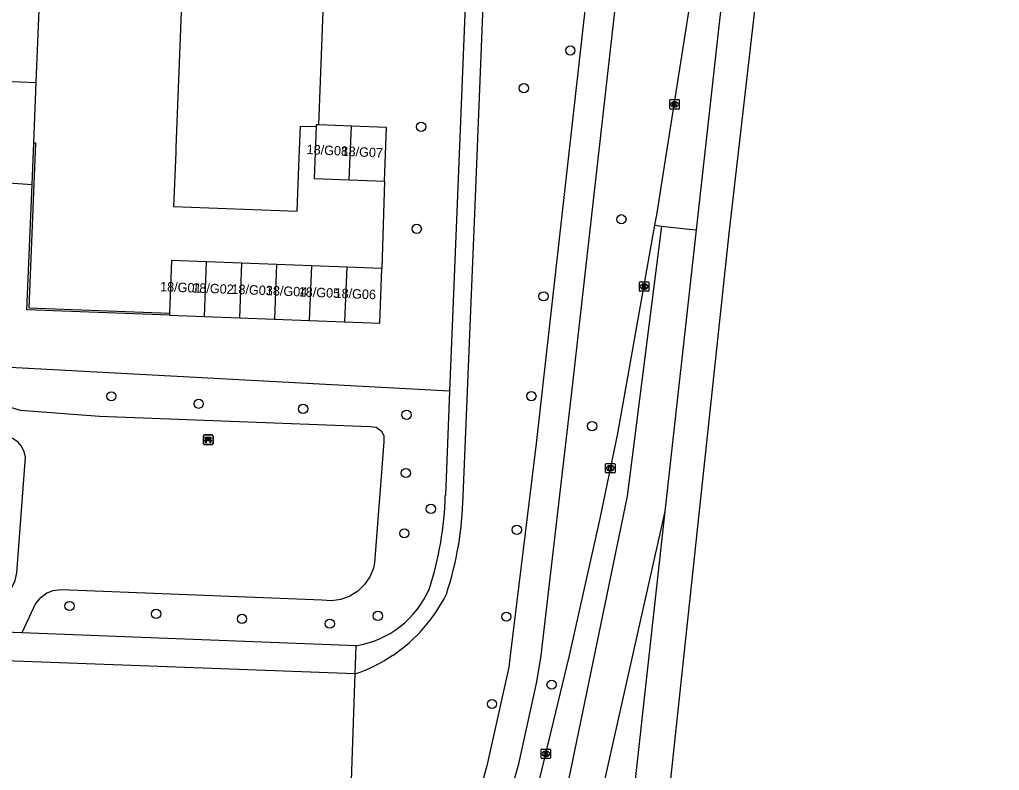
# Model space of a CAD drawing. Extents: x 161355 to 162026, y 386504 to 387459.
# Drawn here: x 161878.2 to 161982, y 386737.8 to 386817.3 of the extents above; entities that cross this region are included whole.
import ezdxf

# ---------------------------------------------------------------- set-up
doc = ezdxf.new("R2010")
doc.units = 0
for name, color, linetype in [('IMGEO_Bank', 7, 'Continuous'), ('IMGEO_Boom', 7, 'Continuous'), ('IMGEO_Fietspad_gesloten', 7, 'Continuous'), ('IMGEO_Groenvoorziening', 7, 'Continuous'), ('IMGEO_Kolk', 7, 'Continuous'), ('IMGEO_Loofbos', 7, 'Continuous'), ('IMGEO_Muur', 7, 'Continuous'), ('IMGEO_Pand', 7, 'Continuous'), ('IMGEO_Pand_nummerreeks', 7, 'Continuous'), ('IMGEO_Rijbaan_regionaal_gesloten', 7, 'Continuous'), ('IMGEO_Voetpad_halfverhard', 7, 'Continuous'), ('IMGEO_Voetpad_open', 7, 'Continuous')]:
    doc.layers.add(name, color=color, linetype=linetype)

msp = doc.modelspace()

# ---------------------------------------------------------------- linework, layer by layer
at = {"layer": 'IMGEO_Bank'}
for p, q in [((161897.72, 386772.41), (161897.72, 386773.25)), ((161897.72, 386773.25), (161897.72, 386772.41)), ((161897.79, 386773.34), (161898.63, 386773.34)), ((161898.63, 386773.34), (161897.79, 386773.34)), ((161898.03, 386772.84), (161898.03, 386772.95)), ((161898.07, 386772.95), (161898.07, 386772.84)), ((161898.36, 386772.95), (161898.08, 386772.95)), ((161898.08, 386772.84), (161898.36, 386772.84)), ((161898.36, 386772.84), (161898.36, 386772.95)), ((161898.41, 386772.95), (161898.41, 386772.84)), ((161898.72, 386773.26), (161898.72, 386772.42)), ((161898.72, 386772.42), (161898.72, 386773.26)), ((161898.64, 386772.34), (161897.8, 386772.34)), ((161897.8, 386772.34), (161898.64, 386772.34)), ((161898.41, 386772.73), (161898.02, 386772.73))]:
    msp.add_line(p, q, dxfattribs=at)
for points in [[(161897.96, 386772.73), (161897.82, 386772.73), (161897.93, 386772.84), (161898.02, 386772.84)], [(161898.02, 386772.95), (161897.93, 386772.95), (161897.93, 386773.12), (161898.5, 386773.12), (161898.5, 386772.95), (161898.41, 386772.95)], [(161898.41, 386772.84), (161898.5, 386772.84), (161898.61, 386772.73), (161898.47, 386772.73)], [(161898.01, 386772.73), (161898.01, 386772.52), (161897.97, 386772.52), (161897.97, 386772.73)], [(161898.46, 386772.73), (161898.46, 386772.52), (161898.42, 386772.52), (161898.42, 386772.73)]]:
    msp.add_lwpolyline(points, dxfattribs=at)
for centre, radius, start, end in [((161897.79, 386773.26), 0.0779, 92.4484, 184.2845), ((161897.79, 386773.26), 0.0779, 92.4484, 184.2845), ((161898.02, 386772.95), 0.00671, 2.8957, 87.1043), ((161898.02, 386772.84), 0.00671, 272.8957, 357.1043), ((161898.08, 386772.95), 0.00671, 92.8957, 177.1043), ((161898.08, 386772.84), 0.00671, 182.8957, 267.1043), ((161898.36, 386772.95), 0.00671, 2.8957, 87.1043), ((161898.36, 386772.84), 0.00671, 272.8957, 357.1043), ((161898.41, 386772.95), 0.00671, 92.8957, 177.1043), ((161898.41, 386772.84), 0.00671, 182.8957, 267.1043), ((161898.64, 386773.26), 0.0779, 2.4484, 94.2845), ((161898.64, 386773.26), 0.0779, 2.4484, 94.2845), ((161897.79, 386772.41), 0.0779, 182.4484, 274.2845), ((161897.79, 386772.41), 0.0779, 182.4484, 274.2845), ((161897.96, 386772.73), 0.00671, 2.8957, 87.1043), ((161898.02, 386772.73), 0.00671, 92.8957, 177.1043), ((161898.41, 386772.73), 0.00671, 2.8957, 87.1043), ((161898.47, 386772.73), 0.00671, 92.8957, 177.1043), ((161898.64, 386772.41), 0.0779, 272.4484, 4.2845), ((161898.64, 386772.41), 0.0779, 272.4484, 4.2845)]:
    msp.add_arc(centre, radius, start, end, dxfattribs=at)
at = {"layer": 'IMGEO_Boom'}
for centre in [(161936.55, 386814.07), (161931.63, 386810.08), (161920.76, 386805.99), (161941.96, 386796.19), (161920.29, 386795.18), (161933.72, 386788.03), (161887.95, 386777.44), (161897.2, 386776.65), (161932.43, 386777.45), (161908.26, 386776.11), (161919.21, 386775.48), (161938.86, 386774.28), (161919.14, 386769.31), (161921.79, 386765.51), (161930.89, 386763.3), (161918.98, 386762.92), (161883.53, 386755.23), (161892.7, 386754.39), (161901.79, 386753.86), (161916.18, 386754.18), (161929.78, 386754.1), (161911.08, 386753.35), (161934.57, 386746.89), (161928.26, 386744.85)]:
    msp.add_circle(centre, 0.489, dxfattribs=at)
at = {"layer": 'IMGEO_Fietspad_gesloten'}
for points in [[(161909.58, 386666.42), (161913.47, 386677.41), (161920.09, 386699.56), (161931.11, 386738.49), (161933.02, 386747.21), (161933.45, 386750), (161936.82, 386778.78), (161938.8, 386796.29), (161960.38, 386987.71), (161961.64, 387000), (161967.26, 387050.92)], [(161964.19, 387051.22), (161958.49, 387000), (161935.66, 386796.64), (161932.95, 386772.44), (161930.2, 386750), (161930.04, 386748.73), (161927.7, 386738.29), (161921.99, 386717.64), (161913.78, 386689.39)]]:
    msp.add_lwpolyline(points, dxfattribs=at)
at = {"layer": 'IMGEO_Groenvoorziening'}
for points in [[(161879.74, 386804.29), (161880, 386810.68)], [(161874.59, 386800.22), (161879.56, 386799.87)], [(161923.76, 386778), (161873.88, 386780.66)], [(161873.76, 386777.33), (161878.31, 386775.97), (161886.7, 386775.33), (161915.37, 386774.23), (161915.99, 386774.16), (161916.54, 386773.78), (161916.79, 386773.3), (161916.8, 386772.63), (161915.83, 386759.8), (161915.71, 386759.25), (161915.33, 386758.32), (161914.77, 386757.49), (161914.05, 386756.8), (161913.2, 386756.27), (161912.25, 386755.93), (161911.26, 386755.79), (161910.26, 386755.86), (161882.65, 386756.95), (161881.75, 386756.83), (161881.14, 386756.59), (161880.35, 386756), (161879.94, 386755.48), (161878.49, 386752.39)], [(161872.93, 386754.57), (161873.86, 386754.63), (161874.7, 386754.87), (161875.57, 386755.27), (161876.27, 386755.79), (161876.92, 386756.42), (161877.38, 386757.12), (161877.76, 386757.93), (161877.95, 386758.75), (161878.85, 386770.99), (161878.73, 386771.6), (161878.42, 386772.18), (161878.04, 386772.61), (161877.5, 386772.98), (161873.66, 386774.7)]]:
    msp.add_lwpolyline(points, dxfattribs=at)
at = {"layer": 'IMGEO_Kolk'}
for p, q in [((161947.09, 386807.94), (161947.09, 386808.79)), ((161947.17, 386808.86), (161948.02, 386808.86)), ((161947.58, 386808.64), (161947.6, 386808.64)), ((161947.6, 386808.08), (161947.58, 386808.08)), ((161948.09, 386808.79), (161948.09, 386807.94)), ((161948.02, 386807.86), (161947.17, 386807.86)), ((161943.87, 386788.63), (161943.87, 386789.49)), ((161943.94, 386789.56), (161944.79, 386789.56)), ((161944.87, 386789.49), (161944.87, 386788.63)), ((161944.79, 386788.56), (161943.94, 386788.56)), ((161944.35, 386789.34), (161944.38, 386789.34)), ((161944.38, 386788.78), (161944.35, 386788.78)), ((161940.29, 386769.39), (161940.29, 386770.24)), ((161940.36, 386770.32), (161941.21, 386770.32)), ((161940.78, 386770.1), (161940.8, 386770.1)), ((161941.29, 386770.24), (161941.29, 386769.39)), ((161941.21, 386769.32), (161940.36, 386769.32)), ((161940.8, 386769.54), (161940.77, 386769.54)), ((161933.45, 386739.15), (161933.45, 386740)), ((161933.52, 386740.07), (161934.38, 386740.07)), ((161933.94, 386739.85), (161933.96, 386739.85)), ((161934.45, 386740), (161934.45, 386739.15)), ((161934.38, 386739.07), (161933.52, 386739.07)), ((161933.96, 386739.29), (161933.93, 386739.29))]:
    msp.add_line(p, q, dxfattribs=at)
for points in [[(161947.09, 386807.94), (161947.09, 386808.79)], [(161947.17, 386808.86), (161948.02, 386808.86)], [(161947.41, 386808.56), (161947.54, 386808.56), (161947.54, 386808.41), (161947.66, 386808.56), (161947.83, 386808.56), (161947.68, 386808.41), (161947.84, 386808.16), (161947.68, 386808.16), (161947.6, 386808.33), (161947.54, 386808.26), (161947.54, 386808.16), (161947.41, 386808.16), (161947.41, 386808.56)], [(161948.09, 386808.79), (161948.09, 386807.94)], [(161948.02, 386807.86), (161947.17, 386807.86)], [(161943.87, 386788.63), (161943.87, 386789.49)], [(161943.94, 386789.56), (161944.79, 386789.56)], [(161944.87, 386789.49), (161944.87, 386788.63)], [(161944.79, 386788.56), (161943.94, 386788.56)], [(161944.19, 386789.26), (161944.31, 386789.26), (161944.31, 386789.11), (161944.44, 386789.26), (161944.6, 386789.26), (161944.46, 386789.11), (161944.61, 386788.86), (161944.46, 386788.86), (161944.37, 386789.02), (161944.31, 386788.96), (161944.31, 386788.86), (161944.19, 386788.86), (161944.19, 386789.26)], [(161940.29, 386769.39), (161940.29, 386770.24)], [(161940.36, 386770.32), (161941.21, 386770.32)], [(161940.61, 386770.02), (161940.73, 386770.02), (161940.73, 386769.87), (161940.86, 386770.02), (161941.03, 386770.02), (161940.88, 386769.87), (161941.03, 386769.62), (161940.88, 386769.62), (161940.8, 386769.78), (161940.73, 386769.71), (161940.73, 386769.62), (161940.61, 386769.62), (161940.61, 386770.02)], [(161941.29, 386770.24), (161941.29, 386769.39)], [(161941.21, 386769.32), (161940.36, 386769.32)], [(161933.45, 386739.15), (161933.45, 386740)], [(161933.52, 386740.07), (161934.38, 386740.07)], [(161933.77, 386739.77), (161933.89, 386739.77), (161933.89, 386739.62), (161934.02, 386739.77), (161934.19, 386739.77), (161934.04, 386739.62), (161934.19, 386739.37), (161934.04, 386739.37), (161933.96, 386739.54), (161933.89, 386739.47), (161933.89, 386739.37), (161933.77, 386739.37), (161933.77, 386739.77)], [(161934.45, 386740), (161934.45, 386739.15)], [(161934.38, 386739.07), (161933.52, 386739.07)]]:
    msp.add_lwpolyline(points, dxfattribs=at)
for centre, start, end in [((161947.17, 386808.79), 91.552, 178.448), ((161947.17, 386808.79), 91.552, 178.448), ((161948.02, 386808.79), 1.552, 88.448), ((161948.02, 386808.79), 1.552, 88.448), ((161947.17, 386807.94), 181.552, 268.448), ((161947.17, 386807.94), 181.552, 268.448), ((161948.02, 386807.94), 271.552, 358.448), ((161948.02, 386807.94), 271.552, 358.448), ((161943.94, 386789.48), 91.552, 178.448), ((161943.94, 386789.48), 91.552, 178.448), ((161944.79, 386789.48), 1.552, 88.448), ((161944.79, 386789.48), 1.552, 88.448), ((161943.94, 386788.64), 181.552, 268.448), ((161943.94, 386788.64), 181.552, 268.448), ((161944.79, 386788.64), 271.552, 358.448), ((161944.79, 386788.64), 271.552, 358.448), ((161940.36, 386770.24), 91.552, 178.448), ((161940.36, 386770.24), 91.552, 178.448), ((161941.21, 386770.24), 1.552, 88.448), ((161941.21, 386770.24), 1.552, 88.448), ((161940.36, 386769.39), 181.552, 268.448), ((161940.36, 386769.39), 181.552, 268.448), ((161941.21, 386769.39), 271.552, 358.448), ((161941.21, 386769.39), 271.552, 358.448), ((161933.53, 386740), 91.552, 178.448), ((161933.53, 386740), 91.552, 178.448), ((161934.37, 386740), 1.552, 88.448), ((161934.37, 386740), 1.552, 88.448), ((161933.53, 386739.15), 181.552, 268.448), ((161933.53, 386739.15), 181.552, 268.448), ((161934.37, 386739.15), 271.552, 358.448), ((161934.37, 386739.15), 271.552, 358.448)]:
    msp.add_arc(centre, 0.0765, start, end, dxfattribs=at)
for centre, major_axis, ratio, start_param, end_param in [((161947.58, 386808.36), (-0.387, 0.002), 0.722429, 4.712389, 7.853982), ((161947.6, 386808.36), (-0.39, 0.002), 0.717154, 1.570796, 4.712389), ((161944.35, 386789.06), (-0.387, 0.002), 0.722429, 4.712389, 7.853982), ((161944.38, 386789.06), (-0.39, 0.002), 0.717154, 1.570796, 4.712389), ((161940.77, 386769.82), (-0.387, 0.002), 0.722429, 4.712389, 7.853982), ((161940.8, 386769.82), (-0.39, 0.002), 0.717154, 1.570796, 4.712389), ((161933.94, 386739.57), (-0.387, 0.002), 0.722429, 4.712389, 7.853982), ((161933.96, 386739.57), (-0.39, 0.002), 0.717154, 1.570796, 4.712389)]:
    msp.add_ellipse(centre, major_axis=major_axis, ratio=ratio, start_param=start_param, end_param=end_param, dxfattribs=at)
at = {"layer": 'IMGEO_Loofbos'}
msp.add_lwpolyline([(161911.77, 386689.47), (161913.78, 386748.04)], dxfattribs=at)
at = {"layer": 'IMGEO_Muur'}
for points in [[(161879.74, 386804.29), (161879.94, 386804.28), (161879.22, 386786.8), (161894.11, 386786.23)], [(161879.56, 386799.87), (161879.74, 386804.29)], [(161894.1, 386786.03), (161879.01, 386786.61), (161879.56, 386799.87)], [(161916.86, 386800.24), (161916.59, 386790.98)]]:
    msp.add_lwpolyline(points, dxfattribs=at)
at = {"layer": 'IMGEO_Pand'}
for points in [[(161909.94, 386806.18), (161911.87, 386857.13), (161896.83, 386857.7), (161895.26, 386816.32), (161894.79, 386803.79), (161894.77, 386803.25), (161894.55, 386797.55), (161907.64, 386797.05), (161907.85, 386802.75), (161907.98, 386806.06), (161909.64, 386806)], [(161909.64, 386806), (161909.44, 386800.52), (161913.15, 386800.38)], [(161909.94, 386806.18), (161909.65, 386806.19), (161909.64, 386806)], [(161913.37, 386806.05), (161909.94, 386806.18)], [(161913.15, 386800.38), (161913.37, 386806.05)], [(161913.15, 386800.38), (161916.86, 386800.24), (161917.08, 386805.91), (161913.37, 386806.05)], [(161898.03, 386791.69), (161894.32, 386791.83), (161894.11, 386786.23)], [(161897.81, 386785.88), (161898.03, 386791.69)], [(161901.74, 386791.55), (161898.03, 386791.69)], [(161901.74, 386791.55), (161901.52, 386785.74)], [(161905.45, 386791.4), (161901.74, 386791.55)], [(161905.45, 386791.4), (161905.23, 386785.6)], [(161909.17, 386791.26), (161905.45, 386791.4)], [(161908.94, 386785.46), (161909.17, 386791.26)], [(161912.88, 386791.12), (161909.17, 386791.26)], [(161912.88, 386791.12), (161912.65, 386785.32)], [(161912.65, 386785.32), (161916.37, 386785.18), (161916.59, 386790.98), (161912.88, 386791.12)], [(161894.11, 386786.23), (161894.1, 386786.03)], [(161894.1, 386786.03), (161897.81, 386785.88)], [(161897.81, 386785.88), (161901.52, 386785.74)], [(161901.52, 386785.74), (161905.23, 386785.6)], [(161905.23, 386785.6), (161908.94, 386785.46)], [(161908.94, 386785.46), (161912.65, 386785.32)]]:
    msp.add_lwpolyline(points, dxfattribs=at)
at = {"layer": 'IMGEO_Rijbaan_regionaal_gesloten'}
for points in [[(161975.24, 387050.12), (161969.65, 387000), (161962.33, 386935.47), (161954.58, 386865.29), (161949.34, 386820), (161945.68, 386796.65), (161945.48, 386795.55)], [(161978.47, 387049.8), (161974.35, 387011.24), (161973.14, 387000.21), (161967.66, 386954.87), (161949.87, 386795.06)], [(161981.98, 387049.45), (161976.05, 386997.24), (161962.38, 386873.24), (161953.32, 386794.68), (161940.78, 386677.09), (161933.98, 386612.63), (161933.5, 386609.43), (161932.69, 386601.55), (161929.93, 386573.91), (161926.12, 386532.02)], [(161885.77, 386537.53), (161889.41, 386536.78), (161889.83, 386542.31), (161890.94, 386556.75), (161891.61, 386564.82), (161892.8, 386577.15), (161893.92, 386585.31), (161895.23, 386593.24), (161896.78, 386601.48), (161897.68, 386605.37), (161899.68, 386613.31), (161901.97, 386621.17), (161904.42, 386628.99), (161906.92, 386636.79), (161912.12, 386652.52), (161914.7, 386660.32), (161923.53, 386687.45), (161934.86, 386729.46), (161942.62, 386766.86), (161946.24, 386795.46)], [(161945.48, 386795.55), (161941.55, 386773.5), (161939.69, 386764.51), (161936.42, 386750), (161931.85, 386730.96), (161926.09, 386709.11), (161923.2, 386699.07), (161919.76, 386687.28), (161915.36, 386673.37), (161911.3, 386661.24), (161910.94, 386660.23)], [(161945.48, 386795.55), (161946.24, 386795.46)], [(161946.24, 386795.46), (161949.15, 386795.14), (161949.87, 386795.06)], [(161949.87, 386795.06), (161946.56, 386765.22)], [(161946.56, 386765.22), (161942.59, 386729.49), (161942.44, 386728.02), (161926.42, 386570.32), (161923.25, 386535.82), (161922.93, 386532.15)], [(161946.56, 386765.22), (161945.26, 386759.43), (161938.3, 386728.44)]]:
    msp.add_lwpolyline(points, dxfattribs=at)
at = {"layer": 'IMGEO_Voetpad_halfverhard'}
for points in [[(161925.21, 386766.87), (161926.46, 386797.66), (161928.84, 386856.82), (161934.63, 386878.76)], [(161927.42, 386868.61), (161924.56, 386797.86), (161923.76, 386778)], [(161923.76, 386778), (161923.32, 386766.94)]]:
    msp.add_lwpolyline(points, dxfattribs=at)
for centre, radius, start, end in [((161888.62, 386767.77), 34.7, 342.0341, 358.6274), ((161888.52, 386767.79), 36.7, 342.0593, 358.56), ((161912.28, 386761.08), 10.18, 278.9227, 336.8109), ((161908.37, 386763.99), 16.84, 303.8184, 333.5339), ((161908.41, 386763.84), 16.69, 288.7537, 303.9824)]:
    msp.add_arc(centre, radius, start, end, dxfattribs=at)
at = {"layer": 'IMGEO_Voetpad_open'}
for points in [[(161880, 386810.68), (161882.45, 386870.5)], [(161874.75, 386804.63), (161874.97, 386810.9), (161880, 386810.68)], [(161878.49, 386752.39), (161872.86, 386752.61)], [(161913.86, 386751.02), (161878.49, 386752.39)], [(161913.78, 386748.04), (161913.83, 386750), (161913.86, 386751.02)], [(161913.78, 386748.04), (161872.92, 386749.57)]]:
    msp.add_lwpolyline(points, dxfattribs=at)

# ---------------------------------------------------------------- texts
at = {"layer": 'IMGEO_Pand_nummerreeks'}
for s, rotation, p in [('18/G08', 357.2073, (161908.61, 386803.11)), ('18/G07', 357.2073, (161912.31, 386802.93)), ('18/G01', 357.7299, (161893.1, 386788.57)), ('18/G02', 357.7299, (161896.51, 386788.44)), ('18/G03', 357.7299, (161900.65, 386788.3)), ('18/G04', 357.7299, (161904.3, 386788.16)), ('18/G05', 357.7299, (161907.78, 386788.02)), ('18/G06', 357.7299, (161911.57, 386787.88))]:
    msp.add_text(s, height=1, rotation=rotation, dxfattribs=at).set_placement(p)

doc.saveas('drawing.dxf')
